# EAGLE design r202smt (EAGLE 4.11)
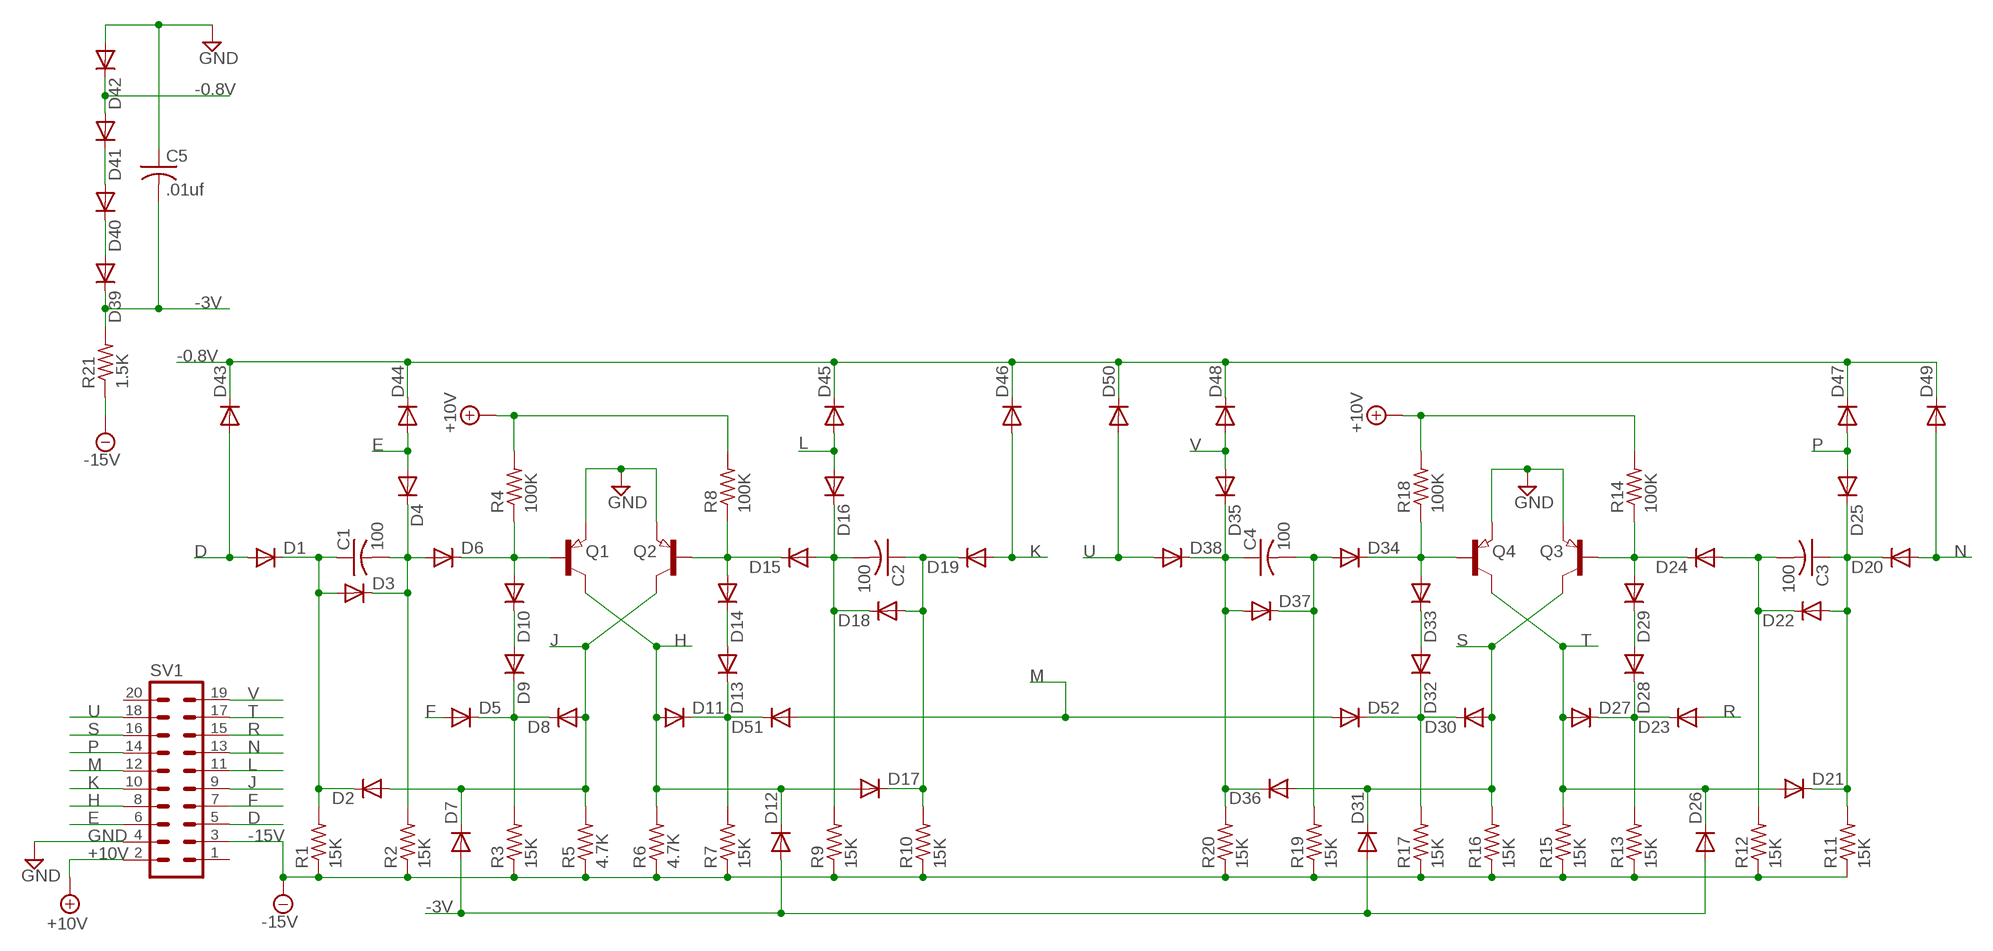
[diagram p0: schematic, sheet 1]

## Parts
C1  100  C-USC0603  [C0603]
C2  100  C-USC0603  [C0603]
C3  100  C-USC0603  [C0603]
C4  100  C-USC0603  [C0603]
C5  .01uf  C-USC1206  [C1206]
D1  DIODE-SOD110-W  [SOD110-W]
D2  DIODE-SOD110-W  [SOD110-W]
D3  DIODE-SOD110-W  [SOD110-W]
D4  DIODE-SOD110-W  [SOD110-W]
D5  DIODE-SOD110-W  [SOD110-W]
D6  DIODE-SOD110-W  [SOD110-W]
D7  DIODE-SOD110-W  [SOD110-W]
D8  DIODE-SOD110-W  [SOD110-W]
D9  DIODE-SOD110-W  [SOD110-W]
D10  DIODE-SOD110-W  [SOD110-W]
D11  DIODE-SOD110-W  [SOD110-W]
D12  DIODE-SOD110-W  [SOD110-W]
D13  DIODE-SOD110-W  [SOD110-W]
D14  DIODE-SOD110-W  [SOD110-W]
D15  DIODE-SOD110-W  [SOD110-W]
D16  DIODE-SOD110-W  [SOD110-W]
D17  DIODE-SOD110-W  [SOD110-W]
D18  DIODE-SOD110-W  [SOD110-W]
D19  DIODE-SOD110-W  [SOD110-W]
D20  DIODE-SOD110-W  [SOD110-W]
D21  DIODE-SOD110-W  [SOD110-W]
D22  DIODE-SOD110-W  [SOD110-W]
D23  DIODE-SOD110-W  [SOD110-W]
D24  DIODE-SOD110-W  [SOD110-W]
D25  DIODE-SOD110-W  [SOD110-W]
D26  DIODE-SOD110-W  [SOD110-W]
D27  DIODE-SOD110-W  [SOD110-W]
D28  DIODE-SOD110-W  [SOD110-W]
D29  DIODE-SOD110-W  [SOD110-W]
D30  DIODE-SOD110-W  [SOD110-W]
D31  DIODE-SOD110-W  [SOD110-W]
D32  DIODE-SOD110-W  [SOD110-W]
D33  DIODE-SOD110-W  [SOD110-W]
D34  DIODE-SOD110-W  [SOD110-W]
D35  DIODE-SOD110-W  [SOD110-W]
D36  DIODE-SOD110-W  [SOD110-W]
D37  DIODE-SOD110-W  [SOD110-W]
D38  DIODE-SOD110-W  [SOD110-W]
D39  DIODE-SOD110-W  [SOD110-W]
D40  DIODE-SOD110-W  [SOD110-W]
D41  DIODE-SOD110-W  [SOD110-W]
D42  DIODE-SOD110-W  [SOD110-W]
D43  DIODE-SOD110-W  [SOD110-W]
D44  DIODE-SOD110-W  [SOD110-W]
D45  DIODE-SOD110-W  [SOD110-W]
D46  DIODE-SOD110-W  [SOD110-W]
D47  DIODE-SOD110-W  [SOD110-W]
D48  DIODE-SOD110-W  [SOD110-W]
D49  DIODE-SOD110-W  [SOD110-W]
D50  DIODE-SOD110-W  [SOD110-W]
D51  DIODE-SOD110-W  [SOD110-W]
D52  DIODE-SOD110-W  [SOD110-W]
Q1  PNP-TRANSISTOR_SOT23  [SOT23]
Q2  PNP-TRANSISTOR_SOT23  [SOT23]
Q3  PNP-TRANSISTOR_SOT23  [SOT23]
Q4  PNP-TRANSISTOR_SOT23  [SOT23]
R1  15K  R-US_R0603  [R0603]
R2  15K  R-US_R0603  [R0603]
R3  15K  R-US_R0603  [R0603]
R4  100K  R-US_R0603  [R0603]
R5  4.7K  R-US_R0603  [R0603]
R6  4.7K  R-US_R0603  [R0603]
R7  15K  R-US_R0603  [R0603]
R8  100K  R-US_R0603  [R0603]
R9  15K  R-US_R0603  [R0603]
R10  15K  R-US_R0603  [R0603]
R11  15K  R-US_R0603  [R0603]
R12  15K  R-US_R0603  [R0603]
R13  15K  R-US_R0603  [R0603]
R14  100K  R-US_R0603  [R0603]
R15  15K  R-US_R0603  [R0603]
R16  15K  R-US_R0603  [R0603]
R17  15K  R-US_R0603  [R0603]
R18  100K  R-US_R0603  [R0603]
R19  15K  R-US_R0603  [R0603]
R20  15K  R-US_R0603  [R0603]
R21  1.5K  R-US_R1206  [R1206]
SV1  MA10-2W  [MA10-2W]

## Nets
+10V: R4.2 R8.2 R14.2 R18.2 SV1.2
-0.8V: D41.A D42.C D43.C D44.C D45.C D46.C D47.C D48.C D49.C D50.C
-3V: C5.2 D7.A D12.A D26.A D31.A D39.C R21.2
-15V: R1.1 R2.1 R3.1 R5.1 R6.1 R7.1 R9.1 R10.1 R11.1 R12.1 R13.1 R15.1 R16.1 R17.1 R19.1 R20.1 R21.1 SV1.3
D: D1.A D43.A SV1.5
E: D4.A D44.A SV1.6
F: D5.A SV1.7
GND: C5.1 D42.A Q1.2(E) Q2.2(E) Q3.2(E) Q4.2(E) SV1.4
H: D11.A D12.C D17.A Q1.3(C) R6.2 SV1.8
J: D2.A D7.C D8.A Q2.3(C) R5.2 SV1.9
K: D19.A D46.A SV1.10
L: D16.A D45.A SV1.11
M: D51.A D52.A SV1.12
N: D20.A D49.A SV1.13
N$1: C1.1 D1.C D2.C D3.A R1.2
N$2: D14.A D15.C Q2.1(B) R8.1
N$3: C1.2 D3.C D4.C D6.A R2.2
N$5: C3.2 D22.C D24.A R12.2
N$6: D6.C D10.A Q1.1(B) R4.1
N$7: D9.A D10.C
N$8: C3.1 D20.C D21.C D22.A D25.C R11.2
N$9: D5.C D8.C D9.C R3.2
N$10: D11.C D13.C D51.C R7.2
N$11: C4.1 D35.C D36.C D37.A D38.C R20.2
N$12: D13.A D14.C
N$13: C2.1 D17.C D18.A D19.C R10.2
N$14: C4.2 D34.A D37.C R19.2
N$15: C2.2 D15.A D16.C D18.C R9.2
N$17: D33.A D34.C Q4.1(B) R18.1
N$23: D32.A D33.C
N$24: D30.C D32.C D52.C R17.2
N$25: D23.C D27.C D28.C R13.2
N$26: D24.C D29.A Q3.1(B) R14.1
N$27: D28.A D29.C
N$30: D39.A D40.C
N$31: D40.A D41.C
P: D25.A D47.A SV1.14
R: D23.A SV1.15
S: D30.A D31.C D36.A Q3.3(C) R16.2 SV1.16
T: D21.A D26.C D27.A Q4.3(C) R15.2 SV1.17
U: D38.A D50.A SV1.18
V: D35.A D48.A SV1.19
Unconnected: SV1.1 SV1.20

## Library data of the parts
C1-C5 = rcl:C-US: CAPACITOR, American symbol
D1-D52 = diode:DIODE-: DIODE
Q1-Q4 = semicon-smd-ipc:PNP-TRANSISTOR_: PNP TRANSISTOR
R1-R21 = rcl:R-US_: RESISTOR, American symbol
SV1 = con-lstb:MA10-2W: PIN HEADER

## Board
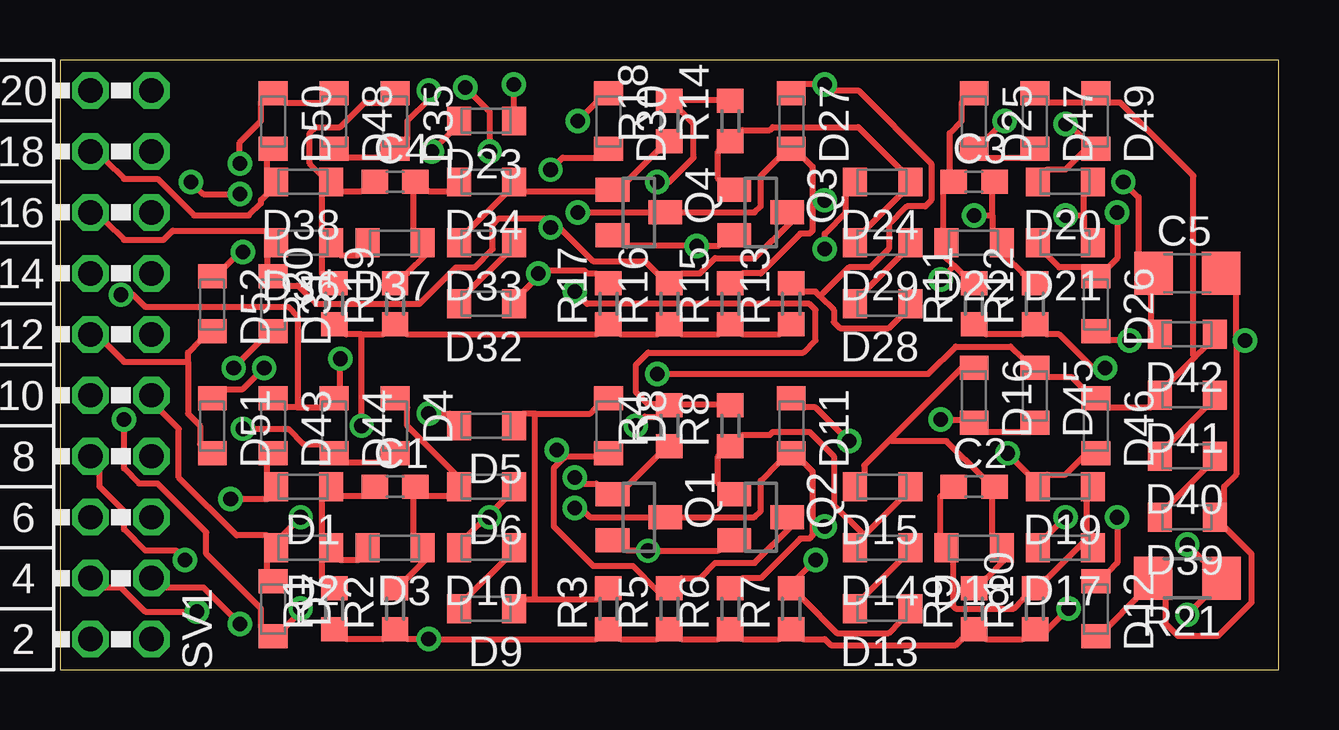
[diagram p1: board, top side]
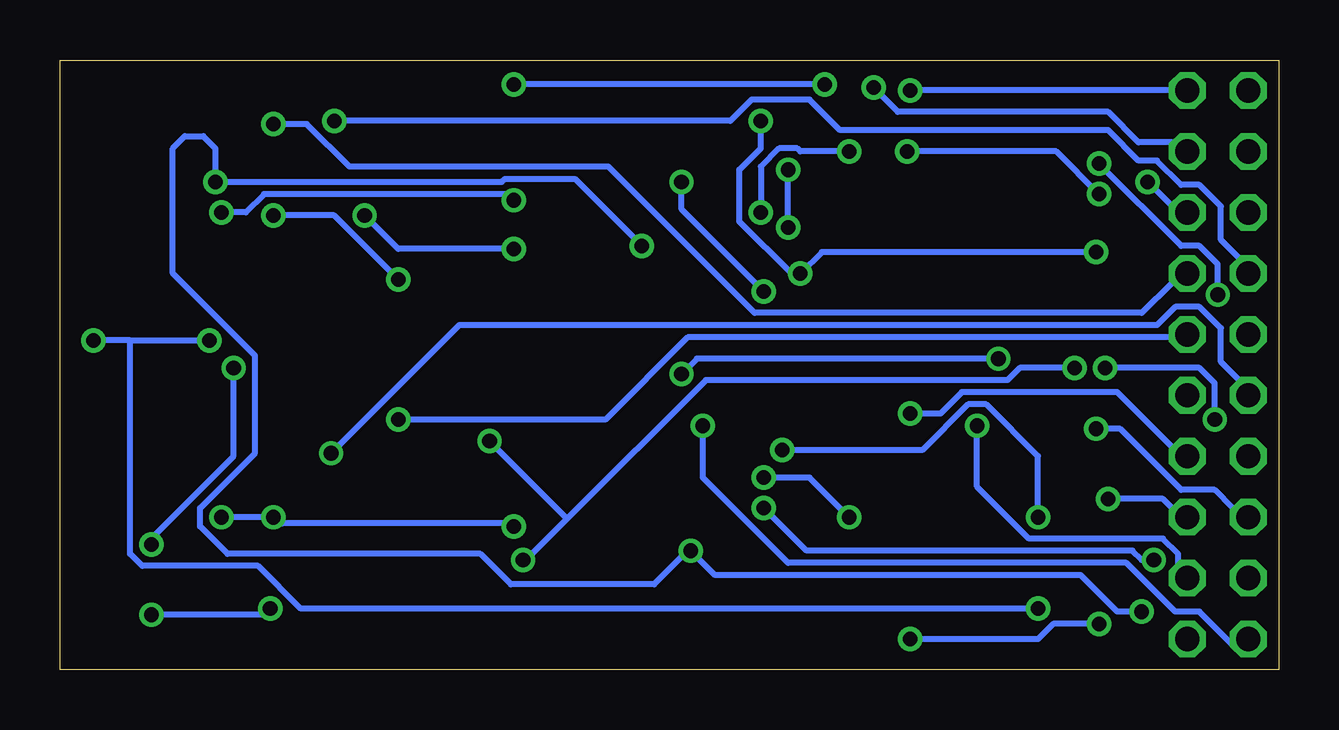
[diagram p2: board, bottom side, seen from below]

Size 50.8 x 25.4 mm. Coordinates in mm from the lower left corner, seen from the top.
Outline: 0,0 50.8,0 50.8,25.4 0,25.4 0,0
Copper layers (1*16): Top 0.035mm / dielectric 1.5mm / Bottom 0.035mm
Design rules "8mils": minimum track width 10mil, minimum drill 24mil, track to track 8mil, track to pad 8mil, pad to pad 8mil, via to via 8mil, smd to smd 8mil, copper to edge 20mil, drill to drill 10mil, minimum pad ring 10mil, minimum via ring 8mil, stop-mask expansion 0mil, vias tented up to drill 0mil, thermal gap 10mil

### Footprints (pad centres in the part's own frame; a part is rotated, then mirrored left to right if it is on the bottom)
C0603 = smd 1.1 x 1: 1 -0.85,0; 2 0.85,0
C1206 = smd 1.6 x 1.8: 1 -1.4,0; 2 1.4,0
SOD110-W = smd 1 x 1.2: A 1.15,0; C -1.15,0
SOT23 = smd 1 x 1.4: 1 -0.95,-1.1; 2 0.95,-1.1; 3 0,1.1
R0603 = smd 1 x 1.1: 1 -0.85,0; 2 0.85,0
R1206 = smd 1.6 x 1.803: 1 -1.422,0; 2 1.422,0
MA10-2W = drill 1.016 octagon: 1 -11.43,-1.27; 2 -11.43,1.27; 3 -8.89,-1.27; 4 -8.89,1.27; 5 -6.35,-1.27; 6 -6.35,1.27; 7 -3.81,-1.27; 8 -3.81,1.27; 9 -1.27,-1.27; 10 -1.27,1.27; 11 1.27,-1.27; 12 1.27,1.27; 13 3.81,-1.27; 14 3.81,1.27; 15 6.35,-1.27; 16 6.35,1.27; 17 8.89,-1.27; 18 8.89,1.27; 19 11.43,-1.27; 20 11.43,1.27

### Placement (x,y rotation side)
C1  13.97,7.62 0 top
C2  38.1,7.62 0 top
C3  38.1,20.32 0 top
C4  13.97,20.32 0 top
C5  46.99,16.51 0 top
D1  10.16,7.62 180 top
D2  10.16,5.08 180 top
D3  13.97,5.08 180 top
D4  13.97,10.16 270 top
D5  17.78,10.16 180 top
D6  17.78,7.62 180 top
D7  8.89,2.54 270 top
D8  22.86,10.16 270 top
D9  17.78,2.54 180 top
D10  17.78,5.08 180 top
D11  30.48,10.16 270 top
D12  43.18,2.54 270 top
D13  34.29,2.54 180 top
D14  34.29,5.08 180 top
D15  34.29,7.62 180 top
D16  38.1,11.43 270 top
D17  41.91,5.08 180 top
D18  38.1,5.08 180 top
D19  41.91,7.62 180 top
D20  41.91,20.32 180 top
D21  41.91,17.78 180 top
D22  38.1,17.78 180 top
D23  17.78,22.86 180 top
D24  34.29,20.32 180 top
D25  38.1,22.86 270 top
D26  43.18,15.24 270 top
D27  30.48,22.86 270 top
D28  34.29,15.24 180 top
D29  34.29,17.78 180 top
D30  22.86,22.86 270 top
D31  8.89,15.24 270 top
D32  17.78,15.24 180 top
D33  17.78,17.78 180 top
D34  17.78,20.32 180 top
D35  13.97,22.86 270 top
D36  10.16,17.78 180 top
D37  13.97,17.78 180 top
D38  10.16,20.32 180 top
D39  46.99,6.35 180 top
D40  46.99,8.89 180 top
D41  46.99,11.43 180 top
D42  46.99,13.97 180 top
D43  8.89,10.16 270 top
D44  11.43,10.16 270 top
D45  40.64,11.43 270 top
D46  43.18,10.16 270 top
D47  40.64,22.86 270 top
D48  11.43,22.86 270 top
D49  43.18,22.86 270 top
D50  8.89,22.86 270 top
D51  6.35,10.16 270 top
D52  6.35,15.24 270 top
Q1  24.13,6.35 270 top
Q2  29.21,6.35 270 top
Q3  29.21,19.05 270 top
Q4  24.13,19.05 270 top
R1  11.43,2.54 90 top
R2  13.97,2.54 90 top
R3  22.86,2.54 90 top
R4  25.4,10.16 90 top
R5  25.4,2.54 90 top
R6  27.94,2.54 90 top
R7  30.48,2.54 90 top
R8  27.94,10.16 90 top
R9  38.1,2.54 90 top
R10  40.64,2.54 90 top
R11  38.1,15.24 90 top
R12  40.64,15.24 90 top
R13  30.48,15.24 90 top
R14  27.94,22.86 90 top
R15  27.94,15.24 90 top
R16  25.4,15.24 90 top
R17  22.86,15.24 90 top
R18  25.4,22.86 90 top
R19  13.97,15.24 90 top
R20  11.43,15.24 90 top
R21  46.99,3.81 180 top
SV1  2.54,12.7 90 top

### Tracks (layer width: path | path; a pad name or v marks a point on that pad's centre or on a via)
+10V  (via drill 0.61)
  Top 0.254: R14.2 27.43,23.75 25.91,23.75 R18.2 25.91,23.24 26.42,22.73 26.42,21.34 25.4,20.32 v24.89,20.32 | R4.2 25.91,11.05 27.43,11.05 R8.2 | v24,10.16 24.38,10.54 24.89,10.54 R4.2 | v21.46,15.75 21.97,15.24 31.24,15.24 31.5,14.99 31.5,13.72 30.99,13.21 24.51,13.21 24,12.7 24,11.56 24.51,11.05 24.89,11.05 R4.2
  Bottom 0.254: v24,10.16 24,8 20.45,4.45 6.35,4.45 4.32,2.41 3.3,2.41 1.91,1.02 SV1.2 | v24.89,20.32 24.89,19.18 v21.46,15.75
-0.8V  (via drill 0.61)
  Top 0.254: D47.C 41.15,23.62 42.67,23.62 D49.C 43.69,23.62 44.2,23.62 47.24,20.57 47.24,13.08 47.31,13.02 | D48.C 10.92,23.62 9.4,23.62 D50.C 8.38,23.62 8.38,22.86 7.49,21.97 v7.49,21.08 | 9.91,10.92 10.92,10.92 D44.C 11.68,11.68 v11.68,12.95 | 9.91,10.92 9.4,10.92 D43.C | 47.31,13.02 46.23,11.94 D41.A 45.47,10.92 43.69,10.92 D46.C 42.67,11.68 42.16,12.19 41.15,12.19 D45.C 40.13,12.95 39.62,13.46 37.34,13.46 36.2,12.32 v24.89,12.32 | 47.31,13.02 47.75,13.46 D42.C | v2.54,15.62 3.05,15.62 3.56,15.11 9.53,15.11 9.91,14.73 9.91,10.92
  Bottom 0.254: v11.68,12.95 24.26,12.95 v24.89,12.32 | v7.49,21.08 4.06,17.65 3.3,17.65 2.54,16.89 v2.54,15.62
-3V  (via drill 0.61)
  Top 0.254: v2.67,10.41 2.67,8.38 3.3,7.75 4.06,7.75 6.1,5.71 6.1,4.83 8.38,2.54 8.38,1.78 D7.A 9.4,1.78 10.03,2.41 v10.03,2.54 | v7.24,12.57 8.38,13.72 D31.A | D12.A 43.69,1.78 44.83,2.92 R21.2 46.1,2.92 46.1,1.91 46.61,1.4 48.26,1.4 49.66,2.79 49.66,4.83 48.51,5.97 D39.C 48.51,6.86 48.51,7.62 49.02,8.13 49.02,13.72 | 49.02,13.72 49.02,15.62 C5.2 | v44.58,13.72 43.69,13.72 D26.A | v49.4,13.72 49.02,13.72
  Bottom 0.254: v2.67,10.41 2.67,11.94 3.3,12.57 v7.24,12.57 | 47.88,13.72 v49.4,13.72 | 47.88,13.72 v44.58,13.72 | v10.03,2.54 40.77,2.54 42.55,4.32 47.37,4.32 47.88,4.83 47.88,13.72
-15V  (via drill 0.61)
  Top 0.254: 12.57,13.97 13.46,13.97 R19.1 14.48,13.97 22.35,13.97 R17.1 23.37,13.97 24.89,13.97 R16.1 25.91,13.97 27.43,13.97 R15.1 28.45,13.97 29.97,13.97 R13.1 | 12.57,13.97 11.94,13.97 R20.1 | v12.57,10.16 12.57,13.97 | R1.1 11.94,1.27 13.46,1.27 R2.1 14.48,1.27 v15.37,1.27 22.35,1.27 R3.1 23.37,1.27 24.89,1.27 R5.1 25.91,1.27 27.43,1.27 R6.1 28.45,1.27 29.97,1.27 R7.1 30.99,1.27 31.88,1.27 32.13,1.02 37.34,1.02 37.59,1.27 R9.1 38.61,1.27 40.13,1.27 R10.1 41.15,1.65 v42.04,2.54 | R11.1 38.61,13.97 40.13,13.97 R12.1 41.15,13.97 41.66,13.97 43.05,12.57 v43.56,12.57 | v46.99,2.29 47.62,2.92 R21.1 47.62,4.57 v46.99,5.21 | v7.49,1.91 5.97,3.43 4.45,3.43 SV1.3
  Bottom 0.254: v12.57,10.16 12.57,7.62 10.41,5.46 4.83,5.46 4.19,4.83 4.19,4.45 SV1.3 | v46.99,2.29 42.29,2.29 v42.04,2.54 | v43.56,12.57 43.56,8.89 46.99,5.46 v46.99,5.21 | v7.49,1.91 9.4,1.91 10.03,1.27 v15.37,1.27
D  (via drill 0.61)
  Top 0.254: D43.A 8.64,8.64 8.64,8.13 D1.A 8.64,7.11 v7.11,7.11
  Bottom 0.254: v7.11,7.11 4.83,7.11 4.45,6.73 SV1.5
E  (via drill 0.61)
  Top 0.254: D4.A 13.46,8.64 11.94,8.64 D44.A 10.92,9.4 10.16,9.4 9.53,10.03 v7.62,10.03
  Bottom 0.254: v7.62,10.03 6.6,10.03 4.06,7.49 2.67,7.49 1.91,6.73 SV1.6
F  (via drill 0.61)
  Top 0.254: v15.37,10.67 16.26,10.67 D5.A
  Bottom 0.254: v15.37,10.67 14.1,10.67 13.21,11.56 6.73,11.56 4.45,9.27 SV1.7
GND  (via drill 0.61)
  Top 0.254: D42.A 45.47,14.48 45.47,15.62 C5.1 44.96,17.4 44.96,19.68 v44.32,20.32 | Q4.2 23.62,17.65 v26.54,17.65 27.43,17.65 Q3.2 | Q1.2 23.62,4.95 v24.51,4.95 27.43,4.95 Q2.2 | v5.71,2.41 3.56,2.41 2.54,3.43 1.91,3.43 SV1.4
  Bottom 0.254: v26.54,17.65 29.34,20.45 32.26,20.45 32.38,20.32 v44.32,20.32 44.32,21.72 44.83,22.23 45.59,22.23 46.1,21.72 46.1,16.51 42.67,13.08 42.67,9.02 44.96,6.73 44.96,5.97 43.81,4.83 33.27,4.83 32,3.56 26.04,3.56 24.89,4.7 v24.51,4.95 23.5,3.94 8.26,3.94 6.73,2.41 v5.71,2.41
H  (via drill 0.61)
  Top 0.254: v41.91,6.35 41.15,5.59 D17.A | v44.07,6.35 44.07,4.45 43.69,4.06 D12.C | 31.37,5.97 31.37,8.26 30.99,8.64 D11.A 29.97,8.64 29.21,7.87 29.21,6.6 28.96,6.35 Q1.3 22.1,6.35 21.72,6.73 v21.46,6.73 | 31.37,5.97 31.37,5.59 31.24,5.46 30.86,5.46 29.21,3.81 28.45,3.81 R6.2 | 31.37,5.97 v31.88,5.97 | v5.21,4.57 4.83,4.95 3.56,4.95 2.67,5.84 2.67,6.6 1.65,7.62 1.65,8.26 SV1.8
  Bottom 0.254: v44.07,6.35 v41.91,6.35 41.53,6.1 32,6.1 v31.88,5.97 | v5.21,4.57 5.71,4.57 6.1,4.95 19.68,4.95 v21.46,6.73
J  (via drill 0.61)
  Top 0.254: Q2.3 30.48,5.97 28.96,4.45 27.3,4.45 26.67,3.81 25.91,3.81 R5.2 24.89,3.3 23.88,4.32 22.23,4.32 20.57,5.97 20.57,8.38 21.02,8.83 | 21.02,8.83 21.08,8.89 22.35,8.89 D8.A | D7.C 8.64,4.06 8.64,4.57 D2.A | D2.A 8.64,5.59 7.37,5.59 4.95,8 4.95,10.03 4.19,10.79 SV1.9 | v10.03,6.35 9.27,5.59 D2.A | v20.7,9.14 21.02,8.83
  Bottom 0.254: v20.7,9.14 14.86,9.14 12.95,11.05 12.19,11.05 10.03,8.89 v10.03,6.35
K  (via drill 0.61)
  Top 0.254: D46.A 42.67,8.89 41.91,8.13 41.15,8.13 D19.A 40.39,8.13 v39.5,9.02
  Bottom 0.254: v39.5,9.02 34.16,14.35 5.08,14.35 4.32,15.11 3.3,15.11 2.41,14.22 2.41,12.83 1.65,12.06 SV1.10
L  (via drill 0.61)
  Top 0.254: D45.A 40.13,9.91 38.61,9.91 D16.A 37.59,10.41 v36.7,10.41
  Bottom 0.254: v36.7,10.41 28.07,10.41 24.64,13.84 4.45,13.84 SV1.11
M
  Top 0.254: 5.33,12.83 5.33,13.21 5.84,13.72 D52.A | 5.33,12.83 5.33,10.67 5.84,10.16 5.84,9.4 D51.A | 5.33,12.83 2.67,12.83 1.91,13.59 SV1.12
N  (via drill 0.61)
  Top 0.254: D20.A 41.15,20.83 41.91,20.83 42.67,21.59 D49.A 42.67,22.1 42.04,22.73 v41.91,22.73
  Bottom 0.254: v41.91,22.73 40.51,22.73 38.73,20.95 27.94,20.95 21.84,14.86 5.71,14.86 4.45,16.13 SV1.13
N$1
  Top 0.254: C1.1 12.57,7.24 11.68,7.24 D1.C 10.92,7.11 10.92,5.59 D2.C | R1.2 10.92,3.81 10.92,4.57 D2.C | D3.A 12.45,4.57 11.68,4.57 D2.C
N$2
  Top 0.254: Q2.1 27.43,7.75 27.43,8.89 R8.1 28.45,9.78 29.59,9.78 29.72,9.91 31.24,9.91 32.26,8.89 32.26,6.86 33.53,5.59 | 33.53,5.59 35.05,7.11 D15.C | 33.53,5.59 D14.A
N$3
  Top 0.254: R2.2 14.48,3.81 15.24,4.57 D3.C 14.73,5.59 14.73,7.24 C1.2 15.37,7.24 16.26,7.24 D6.A 16.51,8.13 14.48,10.16 14.48,10.92 D4.C
N$5  (via drill 0.61)
  Top 0.254: R12.2 40.13,16.51 39.37,17.27 D22.C 38.86,18.29 38.86,18.92 | 38.86,18.92 38.86,19.94 C3.2 | v31.88,17.53 31.88,18.16 32.77,19.05 32.77,19.81 D24.A | v38.1,18.92 38.86,18.92
  Bottom 0.254: v31.88,17.53 36.7,17.53 v38.1,18.92
N$6  (via drill 0.61)
  Top 0.254: R4.1 24.89,8.89 23.62,7.62 Q1.1 22.35,7.75 21.72,7.75 v21.46,8 | 17.84,6.41 18.54,7.11 D6.C | 17.84,6.41 17.02,5.59 D10.A | 17.84,6.41 v17.91,6.35
  Bottom 0.254: v21.46,8 19.56,8 v17.91,6.35
N$7
  Top 0.254: D9.A 17.02,3.05 18.54,4.57 D10.C
N$8  (via drill 0.61)
  Top 0.254: 42.67,18.92 42.67,19.81 D20.C | 42.67,18.92 42.67,18.29 D21.C | 37.27,16.83 36.83,17.27 D22.A 36.83,18.29 36.83,19.94 C3.1 37.08,20.7 37.08,22.35 37.59,22.86 37.59,23.62 D25.C | 37.27,16.83 37.59,16.51 R11.2 | v41.91,18.92 42.67,18.92 | v36.7,16.26 37.27,16.83
  Bottom 0.254: v41.91,18.92 39.37,18.92 v36.7,16.26
N$9
  Top 0.254: 19.81,2.92 19.3,2.92 D9.C | 19.81,2.92 22.35,2.92 R3.2 | 19.81,10.67 22.1,10.67 22.35,10.92 D8.C | 19.81,10.67 19.3,10.67 D5.C | 19.81,2.92 19.81,10.67
N$10  (via drill 0.61)
  Top 0.254: D13.C 35.05,2.03 34.54,1.52 32.38,1.52 30.99,2.92 R7.2 30.73,3.81 v31.5,4.57 | v8.51,12.57 7.62,11.68 6.86,11.68 D51.C | v32.89,9.53 31.5,10.92 30.99,10.92 D11.C
  Bottom 0.254: v8.51,12.57 10.79,12.57 11.3,12.06 23.88,12.06 29.65,6.29 | 29.65,6.29 31.37,4.57 v31.5,4.57 | 29.65,6.29 v32.89,9.53
N$11
  Top 0.254: R20.2 10.92,16.51 10.92,17.27 D36.C | D37.A 12.45,17.27 11.68,17.27 D36.C | C4.1 12.57,19.94 11.68,19.94 D38.C | D35.C 13.46,23.62 12.7,23.62 11.68,22.61 10.67,22.61 10.41,22.35 10.41,21.08 10.92,20.57 D38.C | D36.C 10.92,18.29 10.92,19.81 D38.C
N$12
  Top 0.254: D13.A 33.53,3.05 35.05,4.57 D14.C
N$13
  Top 0.254: C2.1 36.7,7.24 36.7,5.59 D18.A 37.21,4.57 37.21,2.67 37.34,2.54 39.75,2.54 40.13,2.92 R10.2 41.15,3.81 42.67,5.33 D17.C 42.8,5.59 42.8,7.11 D19.C
N$14
  Top 0.254: D34.A 16.26,19.94 15.37,19.94 C4.2 14.73,19.94 14.73,18.29 D37.C 15.24,17.27 14.48,16.51 R19.2
N$15
  Top 0.254: R9.2 38.61,3.81 39.37,4.57 D18.C 38.86,5.59 38.86,7.24 C2.2 38.48,8 36.96,9.53 34.67,9.53 34.61,9.59 | 34.61,9.59 37.59,12.57 D16.C | 34.61,9.59 33.53,8.51 33.53,8.13 D15.A
N$17
  Top 0.254: R18.1 24.89,21.59 23.62,20.32 Q4.1 22.35,19.94 19.3,19.94 D34.C 18.54,19.81 17.02,18.29 D33.A
N$23
  Top 0.254: D32.A 17.02,15.75 18.54,17.27 D33.C
N$24  (via drill 0.61)
  Top 0.254: 20,16.45 19.3,15.75 D32.C | 20,16.45 20.19,16.64 21.84,16.64 21.97,16.51 22.35,16.51 R17.2 | v7.62,17.4 7.49,17.4 6.86,16.76 D52.C | v19.94,16.51 20,16.45 | v21.59,22.86 22.35,23.62 D30.C
  Bottom 0.254: v7.62,17.4 19.05,17.4 v19.94,16.51 20.32,16.51 22.48,18.67 22.48,20.83 21.59,21.72 v21.59,22.86
N$25  (via drill 0.61)
  Top 0.254: 31.69,15.56 32.26,14.99 32.26,14.48 32.51,14.22 34.54,14.22 35.05,14.73 D28.C | 31.69,15.56 31.5,15.75 30.99,15.75 R13.2 | v18.92,24.38 18.92,23.37 D23.C | D27.C 30.99,24.38 v31.88,24.38 32.26,24.13 33.27,24.13 36.32,21.08 36.32,19.56 36.07,19.3 35.31,19.3 34.54,18.54 34.54,17.53 33.78,16.76 32.89,16.76 31.69,15.56
  Bottom 0.254: v18.92,24.38 v31.88,24.38
N$26
  Top 0.254: Q3.1 27.43,20.45 27.43,21.59 R14.1 28.45,22.48 29.59,22.48 29.72,22.61 33.27,22.61 35.05,20.83 D24.C 35.05,19.81 33.53,18.29 D29.A
N$27
  Top 0.254: D28.A 33.53,15.75 35.05,17.27 D29.C
N$30
  Top 0.254: D39.A 46.23,6.86 47.75,8.38 D40.C
N$31
  Top 0.254: D40.A 46.23,9.4 47.75,10.92 D41.C
P  (via drill 0.61)
  Top 0.254: D47.A 40.13,21.34 38.61,21.34 D25.A 38.61,22.1 v39.37,22.86
  Bottom 0.254: v39.37,22.86 22.86,22.86 21.97,23.75 19.56,23.75 18.29,22.48 7.11,22.48 5.84,21.21 5.08,21.21 4.06,20.19 3.3,20.19 2.41,19.3 2.41,17.91 1.65,17.14 SV1.14
R  (via drill 0.61)
  Top 0.254: v15.49,21.59 16.26,22.35 D23.A | v7.49,19.81 5.97,19.81 v5.46,20.32
  Bottom 0.254: v15.49,21.59 9.27,21.59 v7.49,19.81 | v5.46,20.32 4.45,19.3 SV1.15
S  (via drill 0.61)
  Top 0.254: SV1.16 1.91,18.67 2.67,17.91 4.32,17.91 4.7,18.29 8.64,18.29 D36.A 8.64,17.27 8.64,16.76 D31.C 9.4,16 9.91,16 10.67,15.24 14.99,15.24 16.51,16.76 17.27,16.76 18.03,17.53 18.03,18.54 18.29,18.8 20.19,18.8 v20.45,18.41 20.83,18.41 22.23,17.02 24.38,17.02 24.89,16.51 R16.2 25.91,16.51 26.67,16.51 27.3,17.14 28.96,17.14 30.48,18.67 Q3.3 | v20.45,20.83 20.95,21.34 22.35,21.34 D30.A
  Bottom 0.254: v20.45,18.41 v20.45,20.83
T  (via drill 0.61)
  Top 0.254: D21.A 41.15,17.27 41.66,16.76 42.67,16.76 D26.C 43.69,16.76 44.07,17.14 v44.07,19.05 | 31.37,19.56 31.37,20.95 30.99,21.34 D27.A 29.97,21.34 29.21,20.57 29.21,19.3 28.96,19.05 Q4.3 v21.59,19.05 | 31.37,19.56 31.37,18.29 31.24,18.16 30.86,18.16 29.21,16.51 28.45,16.51 R15.2 | 31.37,19.56 v31.88,19.56 | v16.89,24.26 17.91,23.24 v17.91,21.59
  Bottom 0.254: v44.07,19.05 43.05,19.05 42.29,19.81 32.13,19.81 v31.88,19.56 | v16.89,24.26 15.88,23.24 7.11,23.24 5.84,21.97 4.45,21.97 SV1.17 | v17.91,21.59 19.94,21.59 20.07,21.72 20.83,21.72 21.59,20.95 v21.59,19.05
U
  Top 0.254: D50.A 8.64,21.34 8.64,20.83 D38.A 8.64,19.81 8.38,19.56 8.38,19.43 7.87,18.92 5.59,18.92 4.06,20.45 2.67,20.45 1.91,21.21 SV1.18
V  (via drill 0.61)
  Top 0.254: D48.A 11.94,21.34 13.46,21.34 D35.A 14.48,22.1 14.48,22.86 15.37,23.75 v15.37,24.13
  Bottom 0.254: SV1.19 v15.37,24.13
